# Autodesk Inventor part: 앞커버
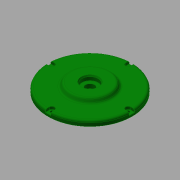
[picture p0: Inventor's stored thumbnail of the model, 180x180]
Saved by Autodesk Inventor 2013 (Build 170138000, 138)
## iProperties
Created: 2016-11
Part Number: 앞커버
Material: 알루미늄 6061
Document SubType Name: Modeling
Designer: mduedu
Density: 2.71 g/cm^3
Mass: 394.828 g
Surface Area: 366.341 cm^2
Volume: 145.693 cm^3
Author: mduedu
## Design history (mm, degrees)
sketch "스케치1"
  geometry: L1 (22, -12.5)-(22, -30); L2 (22, -30)-(16, -33.464); L3 (16, -33.464)-(16, -65); L4 (16, -65)-(8, -65); L5 (8, -65)-(8, -53); L6 (8, -53)-(0, -53); L7 (0, -53)-(0, -14); L8 (0, 0)-(22, 0); L9 (8, -14)-(8, -7); L10 (8, -7)-(14.5, -7); L11 (14.5, -7)-(14.5, -12.5); L12 (0, -14)-(8, -14); L13 (14.5, -12.5)-(22, -12.5)
  constraints: 26 end point, 8 parallel, 3 perpendicular, 2 horizontal, 2 vertical alignment, 1 collinear
  dimensions: "d0" = 8 distance of L5.end L6.end; "d2" = 8 distance of L3.end L4.end; "d3" = 6 distance between parallel lines of L1 L3; "d4" = 120 deg angle of L3 L2; "d5" = 7.5 distance of L11.end L1.start; "d6" = 60 diameter of L1.end L8; "d7" = 14 diameter of L10 L8; "d8" = 28 diameter of L12 L8; "d9" = 25 diameter of L13 L8; "d10" = 106 diameter of L6 L8; "d11" = 130 diameter of L4 L8
revolve "회전1" sketch "스케치1" stored, may be unused: angle "d12" = 90 deg
fillet "모깎기1" dims "d13" = 0.3
fillet "모깎기2" dims "d14" = 3
chamfer "모따기1" distance "d15" = 1; stored, may be unused: second distance "d16" = 2, angle "d17" = 45 deg
fillet "모깎기3" dims "d18" = 0.3
chamfer "모따기2" distance "d36" = 2; stored, may be unused: second distance "d37" = 2, angle "d38" = 30 deg
sketch "스케치3"
  geometry: C1 r 65 at (0, 0) reference; A1 r 59 centre (0, 0) between (0, 59) and (59, 0); 2 further points
  constraints: 4 point on circle, 2 horizontal alignment, 2 vertical alignment, 1 centre point, 1 coincident
  dimensions: "d33" = 118 diameter of A1
sketch "스케치4"
  geometry: 4 further points
  constraints: 4 other
hole "구멍2" sketch "스케치4" at (0, 59), (-59, 0), (59, 0), (0, -59) diameter "d39" = 4.5; stored, may be unused: countersink angle "d43" = 90 deg, drill point angle "d45" = 0 deg; dims "d40" = 6, "d41" = 8, "d42" = 4.6, "d44" = 8
sketch "스케치6"
  geometry: L1 (-4, 5.877)-(-4, 0); L2 (4, 5.877)-(4, 0); A1 r 4 centre (0, 0) between (-2.712, 2.941) and (2.712, 2.941) reference; A2 r 65 centre (0, -59) between (-4, 5.877) and (4, 5.877) reference; 1 further point
  constraints: 4 end point, 4 point on circle, 2 tangent, 2 vertical
extrude "돌출2" cut sketch "스케치6" stored distance "d51" = 10; taper "d52" = 0 deg
fillet "모깎기5" dims "d56" = 0.3
fillet "모깎기6" dims "d57" = 0.3
sketch "스케치5"
  geometry: C1 r 22 at (0, 0); C2 r 45 at (0, 0); 1 further point
  constraints: 2 centre point, 2 coincident
  dimensions: "d46" = 44 diameter of C1; "d47" = 90 diameter of C2
extrude "돌출1" cut sketch "스케치5" distance "d48" = 8; taper "d49" = 0 deg
fillet "모깎기4" dims "d50" = 3
node "솔리드1"
pattern_circular "원형 패턴1" dims angle "d54" = 360 deg
pattern_circular "원형 패턴2" dims angle "d59" = 360 deg
pattern_circular "원형 패턴3" dims angle "d62" = 360 deg
